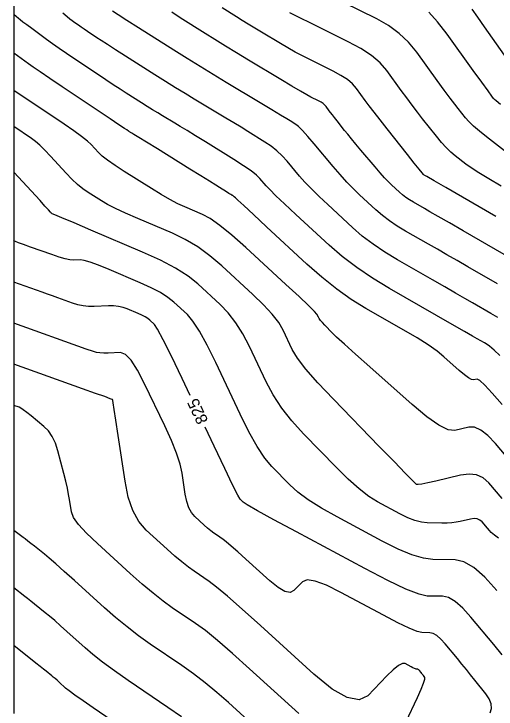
# Model space of a CAD drawing. Extents: x 2082232 to 2083549, y 592624 to 593832.
# Drawn here: x 2082231.79 to 2082260.66, y 593320.25 to 593361.85 of the extents above; entities that cross this region are included whole.
import ezdxf

# ---------------------------------------------------------------- set-up
doc = ezdxf.new("R2010")
doc.units = 0
for name, color, linetype in [('DT_X_Contour_Major', 7, 'Continuous'), ('DT_X_Contour_Minor', 7, 'Continuous'), ('DT_X_TIN_Hull', 7, 'Continuous')]:
    doc.layers.add(name, color=color, linetype=linetype)

msp = doc.modelspace()

# ---------------------------------------------------------------- linework, layer by layer
at = {"layer": 'DT_X_Contour_Major'}
for points in [[(2082260.645, 593349.732), (2082258.634, 593350.89), (2082257.652, 593351.456), (2082256.945, 593351.864), (2082256.514, 593352.115), (2082256.357, 593352.209), (2082256.306, 593352.248), (2082256.233, 593352.333), (2082256.049, 593352.558), (2082255.756, 593352.924), (2082255.353, 593353.43), (2082254.132, 593354.965), (2082253.707, 593355.503), (2082253.347, 593355.965), (2082253.052, 593356.351), (2082252.823, 593356.661), (2082252.297, 593357.387), (2082252.063, 593357.656), (2082251.754, 593357.918), (2082251.369, 593358.173), (2082250.91, 593358.422), (2082249.587, 593359.075), (2082249.099, 593359.321), (2082248.63, 593359.57), (2082248.179, 593359.82), (2082247.747, 593360.073), (2082246.617, 593360.751), (2082246.206, 593360.998), (2082245.82, 593361.234), (2082245.459, 593361.457), (2082245.123, 593361.668), (2082244.259, 593362.213)], [(2082261.019, 593338.48), (2082260.427, 593339.159), (2082259.982, 593339.639), (2082259.681, 593339.92), (2082259.526, 593340), (2082259.306, 593339.948), (2082259.19, 593339.969), (2082259.009, 593340.071), (2082258.763, 593340.255), (2082258.451, 593340.52), (2082257.532, 593341.336), (2082257.124, 593341.665), (2082256.587, 593342.04), (2082255.923, 593342.46), (2082255.131, 593342.926), (2082252.849, 593344.23), (2082251.987, 593344.762), (2082251.113, 593345.381), (2082250.227, 593346.087), (2082249.328, 593346.88), (2082246.917, 593349.111), (2082246.122, 593349.846), (2082245.545, 593350.379), (2082245.187, 593350.71), (2082245.048, 593350.839), (2082244.968, 593350.912), (2082244.941, 593350.937), (2082244.918, 593350.955), (2082244.901, 593350.968), (2082244.888, 593350.976), (2082244.86, 593350.987), (2082244.832, 593351.004), (2082244.765, 593351.044), (2082244.662, 593351.108), (2082244.522, 593351.196), (2082244.097, 593351.464), (2082243.867, 593351.608), (2082243.494, 593351.84), (2082242.978, 593352.16), (2082242.32, 593352.568), (2082240.375, 593353.773), (2082239.733, 593354.171), (2082239.266, 593354.46), (2082238.974, 593354.64), (2082238.856, 593354.713), (2082238.777, 593354.76), (2082238.746, 593354.779), (2082238.713, 593354.799), (2082238.679, 593354.82), (2082238.642, 593354.843), (2082238.543, 593354.906), (2082238.408, 593354.995), (2082238.079, 593355.214), (2082237.557, 593355.563), (2082236.84, 593356.043), (2082234.669, 593357.495), (2082233.933, 593357.989), (2082233.354, 593358.381), (2082232.931, 593358.671), (2082232.665, 593358.86), (2082231.787, 593359.504)], [(2082242.33, 593339.021), (2082241.856, 593340.025), (2082241.214, 593341.366), (2082240.726, 593342.351), (2082240.391, 593342.982), (2082240.208, 593343.257), (2082239.926, 593343.516), (2082239.803, 593343.614), (2082239.645, 593343.713), (2082239.453, 593343.815), (2082239.227, 593343.917), (2082238.577, 593344.194), (2082238.324, 593344.283), (2082238.05, 593344.343), (2082237.757, 593344.374), (2082237.445, 593344.376), (2082236.585, 593344.342), (2082236.262, 593344.346), (2082235.939, 593344.381), (2082235.616, 593344.448), (2082235.292, 593344.548), (2082234.427, 593344.856), (2082234.106, 593344.97), (2082233.791, 593345.082), (2082233.483, 593345.192), (2082231.787, 593345.795)], [(2082261.01, 593323.503), (2082260.513, 593324.105), (2082259.148, 593325.752), (2082258.658, 593326.294), (2082258.211, 593326.682), (2082257.806, 593326.917), (2082257.444, 593326.999), (2082256.535, 593327.013), (2082256.045, 593327.12), (2082255.257, 593327.432), (2082254.171, 593327.947), (2082252.787, 593328.666), (2082248.699, 593330.856), (2082247.349, 593331.583), (2082246.367, 593332.121), (2082245.752, 593332.47), (2082245.505, 593332.631), (2082245.334, 593332.806), (2082245.188, 593333.054), (2082244.879, 593333.665), (2082244.406, 593334.638), (2082243.77, 593335.975), (2082243.228, 593337.123)], [(2082241.821, 593319.79), (2082241.006, 593320.353), (2082238.635, 593321.965), (2082237.807, 593322.54), (2082237.099, 593323.056), (2082236.512, 593323.513), (2082236.045, 593323.911), (2082234.962, 593324.893), (2082234.577, 593325.24), (2082234.232, 593325.542), (2082233.928, 593325.801), (2082233.665, 593326.016), (2082233.019, 593326.53), (2082232.793, 593326.71), (2082232.599, 593326.863), (2082232.438, 593326.991), (2082231.787, 593327.509)]]:
    msp.add_lwpolyline(points, dxfattribs=at)
at = {"layer": 'DT_X_Contour_Minor'}
for points in [[(2082261.331, 593353.513), (2082260.084, 593354.486), (2082259.654, 593354.832), (2082259.299, 593355.138), (2082259.021, 593355.405), (2082258.817, 593355.632), (2082258.377, 593356.187), (2082258.175, 593356.448), (2082257.9, 593356.815), (2082257.552, 593357.288), (2082257.131, 593357.867), (2082255.911, 593359.553), (2082255.417, 593360.153), (2082254.852, 593360.686), (2082254.216, 593361.152), (2082253.508, 593361.553), (2082251.524, 593362.532)], [(2082260.871, 593341.411), (2082260.534, 593341.733), (2082260.403, 593341.851), (2082260.264, 593341.961), (2082260.115, 593342.065), (2082259.957, 593342.161), (2082259.525, 593342.41), (2082259.251, 593342.567), (2082258.754, 593342.852), (2082258.032, 593343.264), (2082257.088, 593343.804), (2082254.27, 593345.413), (2082253.251, 593346.028), (2082252.31, 593346.665), (2082251.447, 593347.324), (2082250.66, 593348.005), (2082248.664, 593349.85), (2082247.992, 593350.476), (2082247.472, 593350.971), (2082247.105, 593351.334), (2082246.889, 593351.566), (2082246.517, 593352.008), (2082246.315, 593352.203), (2082245.987, 593352.455), (2082245.535, 593352.765), (2082244.957, 593353.133), (2082243.25, 593354.191), (2082242.655, 593354.559), (2082242.151, 593354.869), (2082241.738, 593355.121), (2082241.417, 593355.316), (2082240.68, 593355.757), (2082240.395, 593355.93), (2082240.092, 593356.115), (2082239.772, 593356.315), (2082239.433, 593356.527), (2082238.507, 593357.113), (2082238.14, 593357.347), (2082237.731, 593357.613), (2082237.282, 593357.909), (2082236.791, 593358.235), (2082235.429, 593359.146), (2082234.941, 593359.476), (2082234.497, 593359.781), (2082234.097, 593360.062), (2082233.742, 593360.318), (2082232.854, 593360.969), (2082232.555, 593361.19), (2082232.324, 593361.363), (2082232.162, 593361.489), (2082232.067, 593361.567), (2082231.787, 593361.823)], [(2082260.751, 593343.681), (2082260.349, 593343.928), (2082259.247, 593344.562), (2082258.787, 593344.826), (2082258.234, 593345.143), (2082257.587, 593345.514), (2082256.847, 593345.936), (2082254.749, 593347.135), (2082253.991, 593347.593), (2082253.29, 593348.067), (2082252.647, 593348.557), (2082252.061, 593349.064), (2082250.575, 593350.438), (2082250.053, 593350.931), (2082249.598, 593351.379), (2082249.213, 593351.783), (2082248.895, 593352.141), (2082248.141, 593353.038), (2082247.846, 593353.361), (2082247.525, 593353.66), (2082247.18, 593353.935), (2082246.809, 593354.184), (2082245.788, 593354.817), (2082245.388, 593355.064), (2082244.953, 593355.33), (2082244.482, 593355.615), (2082243.977, 593355.918), (2082242.584, 593356.754), (2082242.044, 593357.08), (2082241.471, 593357.432), (2082240.865, 593357.809), (2082240.224, 593358.212), (2082238.472, 593359.319), (2082237.871, 593359.7), (2082237.383, 593360.011), (2082237.007, 593360.254), (2082236.743, 593360.427), (2082236.19, 593360.797), (2082235.991, 593360.931), (2082235.811, 593361.055), (2082235.649, 593361.169), (2082235.504, 593361.273), (2082235.144, 593361.538), (2082234.969, 593361.676), (2082234.716, 593361.891)], [(2082260.741, 593345.694), (2082258.969, 593346.714), (2082258.323, 593347.085), (2082257.714, 593347.435), (2082257.142, 593347.763), (2082256.607, 593348.069), (2082255.228, 593348.856), (2082254.73, 593349.157), (2082254.27, 593349.469), (2082253.847, 593349.791), (2082253.462, 593350.124), (2082252.486, 593351.027), (2082252.113, 593351.386), (2082251.724, 593351.788), (2082251.321, 593352.231), (2082250.902, 593352.717), (2082249.765, 593354.067), (2082249.377, 593354.52), (2082249.063, 593354.866), (2082248.825, 593355.104), (2082248.662, 593355.236), (2082248.327, 593355.443), (2082248.121, 593355.569), (2082247.754, 593355.791), (2082247.226, 593356.108), (2082246.538, 593356.521), (2082244.487, 593357.751), (2082243.715, 593358.218), (2082242.936, 593358.694), (2082242.151, 593359.181), (2082241.36, 593359.678), (2082239.241, 593361.017), (2082238.539, 593361.462), (2082238.025, 593361.792), (2082237.696, 593362.006)], [(2082261.133, 593347.46), (2082258.691, 593348.865), (2082257.859, 593349.344), (2082257.195, 593349.726), (2082256.697, 593350.012), (2082256.366, 593350.202), (2082255.708, 593350.578), (2082255.47, 593350.722), (2082255.25, 593350.87), (2082255.048, 593351.024), (2082254.864, 593351.184), (2082254.397, 593351.615), (2082254.205, 593351.804), (2082253.976, 593352.047), (2082253.711, 593352.344), (2082253.411, 593352.695), (2082252.563, 593353.703), (2082252.263, 593354.06), (2082252.001, 593354.376), (2082251.776, 593354.651), (2082251.589, 593354.883), (2082251.139, 593355.449), (2082250.983, 593355.646), (2082250.853, 593355.813), (2082250.748, 593355.951), (2082250.668, 593356.058), (2082250.491, 593356.304), (2082250.411, 593356.395), (2082250.306, 593356.483), (2082250.176, 593356.57), (2082250.021, 593356.654), (2082249.573, 593356.875), (2082249.334, 593357.003), (2082248.955, 593357.219), (2082248.435, 593357.524), (2082247.773, 593357.919), (2082245.823, 593359.089), (2082245.113, 593359.517), (2082244.446, 593359.923), (2082243.822, 593360.309), (2082243.241, 593360.673), (2082241.75, 593361.615), (2082241.236, 593361.946)], [(2082260.958, 593351.544), (2082260.216, 593351.978), (2082259.616, 593352.342), (2082259.159, 593352.636), (2082258.844, 593352.861), (2082258.195, 593353.367), (2082257.943, 593353.582), (2082257.674, 593353.848), (2082257.388, 593354.164), (2082257.085, 593354.531), (2082256.254, 593355.576), (2082255.941, 593355.975), (2082255.623, 593356.39), (2082255.302, 593356.819), (2082254.977, 593357.264), (2082254.104, 593358.47), (2082253.714, 593358.917), (2082253.201, 593359.352), (2082252.562, 593359.776), (2082251.8, 593360.189), (2082249.601, 593361.275), (2082248.864, 593361.64), (2082248.306, 593361.92)], [(2082260.925, 593356.428), (2082260.653, 593356.645), (2082260.55, 593356.734), (2082260.499, 593356.798), (2082260.409, 593356.92), (2082260.176, 593357.24), (2082259.802, 593357.757), (2082259.285, 593358.47), (2082257.717, 593360.637), (2082257.151, 593361.373), (2082256.627, 593361.958)], [(2082261.163, 593359.374), (2082259.965, 593361.076), (2082259.553, 593361.66), (2082259.218, 593362.135)], [(2082261.906, 593334.623), (2082260.618, 593336.135), (2082260.156, 593336.622), (2082259.737, 593336.949), (2082259.358, 593337.114), (2082259.022, 593337.12), (2082258.182, 593336.92), (2082257.786, 593336.96), (2082257.23, 593337.232), (2082256.514, 593337.735), (2082255.638, 593338.468), (2082253.088, 593340.733), (2082252.23, 593341.497), (2082251.571, 593342.091), (2082251.11, 593342.515), (2082250.846, 593342.769), (2082250.408, 593343.22), (2082250.261, 593343.377), (2082250.146, 593343.508), (2082250.064, 593343.615), (2082250.015, 593343.696), (2082249.928, 593343.88), (2082249.787, 593344.043), (2082249.43, 593344.395), (2082248.856, 593344.937), (2082248.065, 593345.667), (2082245.668, 593347.866), (2082244.832, 593348.609), (2082244.122, 593349.187), (2082243.538, 593349.601), (2082243.081, 593349.851), (2082242.029, 593350.299), (2082241.608, 593350.494), (2082241.132, 593350.743), (2082240.604, 593351.046), (2082240.021, 593351.402), (2082238.395, 593352.426), (2082237.841, 593352.784), (2082237.399, 593353.091), (2082237.068, 593353.347), (2082236.848, 593353.552), (2082236.411, 593354.03), (2082236.188, 593354.241), (2082235.843, 593354.515), (2082235.379, 593354.851), (2082234.795, 593355.251), (2082231.787, 593357.263)], [(2082261.022, 593332.847), (2082260.218, 593333.791), (2082259.885, 593334.085), (2082259.492, 593334.258), (2082259.036, 593334.309), (2082258.519, 593334.239), (2082257.057, 593333.892), (2082256.573, 593333.782), (2082256.217, 593333.713), (2082255.988, 593333.685), (2082255.888, 593333.697), (2082255.789, 593333.785), (2082255.628, 593333.946), (2082255.22, 593334.363), (2082254.563, 593335.036), (2082253.659, 593335.966), (2082250.918, 593338.787), (2082249.992, 593339.767), (2082249.273, 593340.59), (2082248.761, 593341.256), (2082248.454, 593341.766), (2082247.91, 593342.916), (2082247.644, 593343.374), (2082247.254, 593343.884), (2082246.739, 593344.448), (2082246.101, 593345.064), (2082244.232, 593346.779), (2082243.522, 593347.382), (2082242.792, 593347.908), (2082242.042, 593348.357), (2082241.273, 593348.727), (2082239.197, 593349.611), (2082238.478, 593349.925), (2082237.878, 593350.204), (2082237.396, 593350.447), (2082237.033, 593350.656), (2082236.224, 593351.165), (2082235.914, 593351.38), (2082235.593, 593351.644), (2082235.261, 593351.955), (2082234.916, 593352.314), (2082233.982, 593353.337), (2082233.648, 593353.691), (2082233.345, 593353.987), (2082233.074, 593354.224), (2082232.834, 593354.403), (2082231.787, 593355.104)], [(2082260.797, 593330.477), (2082260.558, 593330.655), (2082260.465, 593330.731), (2082260.364, 593330.825), (2082260.255, 593330.939), (2082260.138, 593331.071), (2082259.817, 593331.447), (2082259.684, 593331.564), (2082259.523, 593331.632), (2082259.335, 593331.652), (2082259.121, 593331.622), (2082258.513, 593331.477), (2082258.273, 593331.431), (2082258.008, 593331.399), (2082257.719, 593331.382), (2082257.405, 593331.379), (2082256.535, 593331.393), (2082256.188, 593331.431), (2082255.798, 593331.534), (2082255.365, 593331.703), (2082254.889, 593331.936), (2082253.563, 593332.646), (2082253.036, 593332.974), (2082252.448, 593333.426), (2082251.8, 593334.001), (2082251.091, 593334.7), (2082249.121, 593336.727), (2082248.427, 593337.492), (2082247.825, 593338.265), (2082247.313, 593339.046), (2082246.892, 593339.836), (2082245.892, 593341.952), (2082245.501, 593342.705), (2082245.078, 593343.373), (2082244.623, 593343.959), (2082244.137, 593344.462), (2082242.797, 593345.691), (2082242.213, 593346.156), (2082241.465, 593346.628), (2082240.554, 593347.109), (2082239.48, 593347.597), (2082236.399, 593348.909), (2082235.387, 593349.339), (2082234.664, 593349.647), (2082234.23, 593349.831), (2082234.084, 593349.892), (2082234.081, 593349.892), (2082234.079, 593349.892), (2082234.077, 593349.893), (2082234.074, 593349.894), (2082234.07, 593349.895), (2082234.06, 593349.899), (2082234.056, 593349.901), (2082234.051, 593349.904), (2082234.047, 593349.909), (2082234.042, 593349.914), (2082234.029, 593349.931), (2082233.983, 593349.982), (2082233.854, 593350.124), (2082233.643, 593350.355), (2082233.35, 593350.677), (2082231.787, 593352.387)], [(2082260.69, 593327.353), (2082259.973, 593328.145), (2082259.318, 593328.713), (2082258.725, 593329.057), (2082258.195, 593329.177), (2082256.866, 593329.198), (2082256.302, 593329.273), (2082255.61, 593329.482), (2082254.789, 593329.824), (2082253.838, 593330.301), (2082251.131, 593331.751), (2082250.193, 593332.279), (2082249.408, 593332.774), (2082248.776, 593333.236), (2082248.298, 593333.665), (2082247.227, 593334.767), (2082246.808, 593335.273), (2082246.352, 593335.965), (2082245.86, 593336.842), (2082245.331, 593337.906), (2082243.874, 593340.989), (2082243.358, 593342.035), (2082242.902, 593342.862), (2082242.507, 593343.47), (2082242.172, 593343.859), (2082241.361, 593344.603), (2082241.008, 593344.885), (2082240.555, 593345.171), (2082240.004, 593345.462), (2082239.354, 593345.757), (2082237.488, 593346.551), (2082236.855, 593346.811), (2082236.357, 593346.995), (2082235.994, 593347.103), (2082235.765, 593347.134), (2082235.333, 593347.117), (2082235.132, 593347.133), (2082234.851, 593347.193), (2082234.492, 593347.297), (2082234.053, 593347.445), (2082232.779, 593347.898), (2082232.36, 593348.048), (2082232.059, 593348.157), (2082231.877, 593348.225), (2082231.812, 593348.252), (2082231.787, 593348.285)], [(2082260.299, 593320.028), (2082260.373, 593320.29), (2082260.354, 593320.565), (2082260.244, 593320.855), (2082260.043, 593321.158), (2082259.383, 593321.985), (2082259.132, 593322.297), (2082258.874, 593322.615), (2082258.61, 593322.939), (2082258.339, 593323.268), (2082257.607, 593324.152), (2082257.344, 593324.442), (2082257.103, 593324.65), (2082256.886, 593324.776), (2082256.692, 593324.82), (2082256.204, 593324.828), (2082255.924, 593324.895), (2082255.45, 593325.09), (2082254.781, 593325.412), (2082253.918, 593325.862), (2082251.359, 593327.234), (2082250.495, 593327.659), (2082249.824, 593327.906), (2082249.346, 593327.975), (2082249.061, 593327.867), (2082248.556, 593327.339), (2082248.324, 593327.227), (2082248.005, 593327.286), (2082247.599, 593327.517), (2082247.106, 593327.919), (2082245.677, 593329.22), (2082245.19, 593329.66), (2082244.799, 593330.003), (2082244.504, 593330.249), (2082244.306, 593330.399), (2082243.907, 593330.671), (2082243.749, 593330.784), (2082243.576, 593330.92), (2082243.387, 593331.079), (2082243.182, 593331.261), (2082242.614, 593331.776), (2082242.419, 593332.004), (2082242.259, 593332.302), (2082242.135, 593332.671), (2082242.047, 593333.109), (2082241.857, 593334.373), (2082241.739, 593334.905), (2082241.526, 593335.555), (2082241.218, 593336.321), (2082240.815, 593337.205), (2082239.615, 593339.717), (2082239.186, 593340.54), (2082238.801, 593341.125), (2082238.46, 593341.472), (2082238.162, 593341.58), (2082237.424, 593341.551), (2082237.162, 593341.549), (2082236.929, 593341.563), (2082236.725, 593341.595), (2082236.551, 593341.643), (2082236.123, 593341.796), (2082231.787, 593343.339)], [(2082255.25, 593319.46), (2082255.944, 593320.944), (2082256.168, 593321.436), (2082256.318, 593321.8), (2082256.395, 593322.035), (2082256.398, 593322.142), (2082256.308, 593322.255), (2082256.274, 593322.298), (2082256.238, 593322.341), (2082256.202, 593322.385), (2082256.165, 593322.43), (2082256.065, 593322.551), (2082256.029, 593322.591), (2082255.996, 593322.619), (2082255.967, 593322.636), (2082255.94, 593322.642), (2082255.873, 593322.643), (2082255.835, 593322.653), (2082255.77, 593322.679), (2082255.679, 593322.723), (2082255.561, 593322.785), (2082255.211, 593322.972), (2082255.044, 593322.978), (2082254.803, 593322.857), (2082254.49, 593322.607), (2082254.104, 593322.229), (2082252.977, 593321.05), (2082252.458, 593320.8), (2082251.745, 593320.933), (2082250.838, 593321.448), (2082249.737, 593322.346), (2082246.545, 593325.253), (2082245.455, 593326.235), (2082244.581, 593327.001), (2082243.923, 593327.552), (2082243.481, 593327.888), (2082242.589, 593328.494), (2082242.237, 593328.747), (2082241.849, 593329.051), (2082241.427, 593329.406), (2082240.969, 593329.812), (2082239.701, 593330.962), (2082239.266, 593331.468), (2082238.911, 593332.124), (2082238.636, 593332.929), (2082238.442, 593333.883), (2082238.03, 593336.627), (2082237.895, 593337.529), (2082237.798, 593338.176), (2082237.738, 593338.569), (2082237.716, 593338.707), (2082237.709, 593338.736), (2082237.706, 593338.746), (2082237.702, 593338.755), (2082237.697, 593338.762), (2082237.691, 593338.768), (2082237.674, 593338.782), (2082237.558, 593338.825), (2082237.224, 593338.946), (2082236.671, 593339.144), (2082235.899, 593339.419), (2082231.787, 593340.882)], [(2082248.839, 593319.987), (2082245.899, 593322.663), (2082244.87, 593323.585), (2082243.986, 593324.344), (2082243.248, 593324.942), (2082242.656, 593325.376), (2082241.271, 593326.318), (2082240.724, 593326.711), (2082240.123, 593327.183), (2082239.467, 593327.734), (2082238.756, 593328.364), (2082236.788, 593330.149), (2082236.137, 593330.77), (2082235.66, 593331.293), (2082235.357, 593331.719), (2082235.228, 593332.047), (2082235.117, 593332.791), (2082235.064, 593333.098), (2082234.989, 593333.461), (2082234.892, 593333.88), (2082234.773, 593334.354), (2082234.427, 593335.694), (2082234.277, 593336.163), (2082234.088, 593336.565), (2082233.858, 593336.901), (2082233.588, 593337.169), (2082232.814, 593337.797), (2082232.552, 593338.005), (2082232.345, 593338.161), (2082232.195, 593338.264), (2082232.1, 593338.315), (2082231.787, 593338.426)], [(2082246.502, 593318.936), (2082244.638, 593320.634), (2082243.938, 593321.25), (2082243.237, 593321.828), (2082242.534, 593322.366), (2082241.831, 593322.864), (2082239.953, 593324.141), (2082239.253, 593324.636), (2082238.562, 593325.164), (2082237.879, 593325.723), (2082237.205, 593326.315), (2082235.418, 593327.936), (2082234.803, 593328.491), (2082234.299, 593328.938), (2082233.907, 593329.279), (2082233.625, 593329.512), (2082233.021, 593329.993), (2082232.808, 593330.161), (2082232.623, 593330.306), (2082232.464, 593330.428), (2082232.334, 593330.527), (2082231.787, 593330.935)], [(2082238.372, 593319.071), (2082236.542, 593320.316), (2082235.924, 593320.74), (2082235.442, 593321.08), (2082235.096, 593321.336), (2082234.886, 593321.507), (2082234.507, 593321.85), (2082234.372, 593321.972), (2082234.251, 593322.078), (2082234.145, 593322.168), (2082234.053, 593322.243), (2082233.718, 593322.51), (2082233.559, 593322.636), (2082233.352, 593322.8), (2082233.096, 593323.004), (2082231.787, 593324.045)]]:
    msp.add_lwpolyline(points, dxfattribs=at)
at = {"layer": 'DT_X_TIN_Hull'}
msp.add_lwpolyline([(2082231.787, 593385.022), (2082231.787, 593378.886), (2082231.787, 593377.418), (2082231.787, 593374.63), (2082231.787, 593370.97), (2082231.787, 593365.705), (2082231.787, 593364.517), (2082231.787, 593361.416), (2082231.787, 593357.443), (2082231.787, 593353.951), (2082231.787, 593351.16), (2082231.787, 593348.211), (2082231.787, 593338.224), (2082231.787, 593335.312), (2082231.787, 593331.142), (2082231.787, 593329.814), (2082231.787, 593322.524), (2082231.787, 593319.977)], dxfattribs=at)

# ---------------------------------------------------------------- texts
at = {"layer": 'DT_X_Contour_Major'}
msp.add_text('825', height=0.7, rotation=115.2998, dxfattribs=at).set_placement((2082243.433, 593337.507))

doc.saveas('drawing.dxf')
